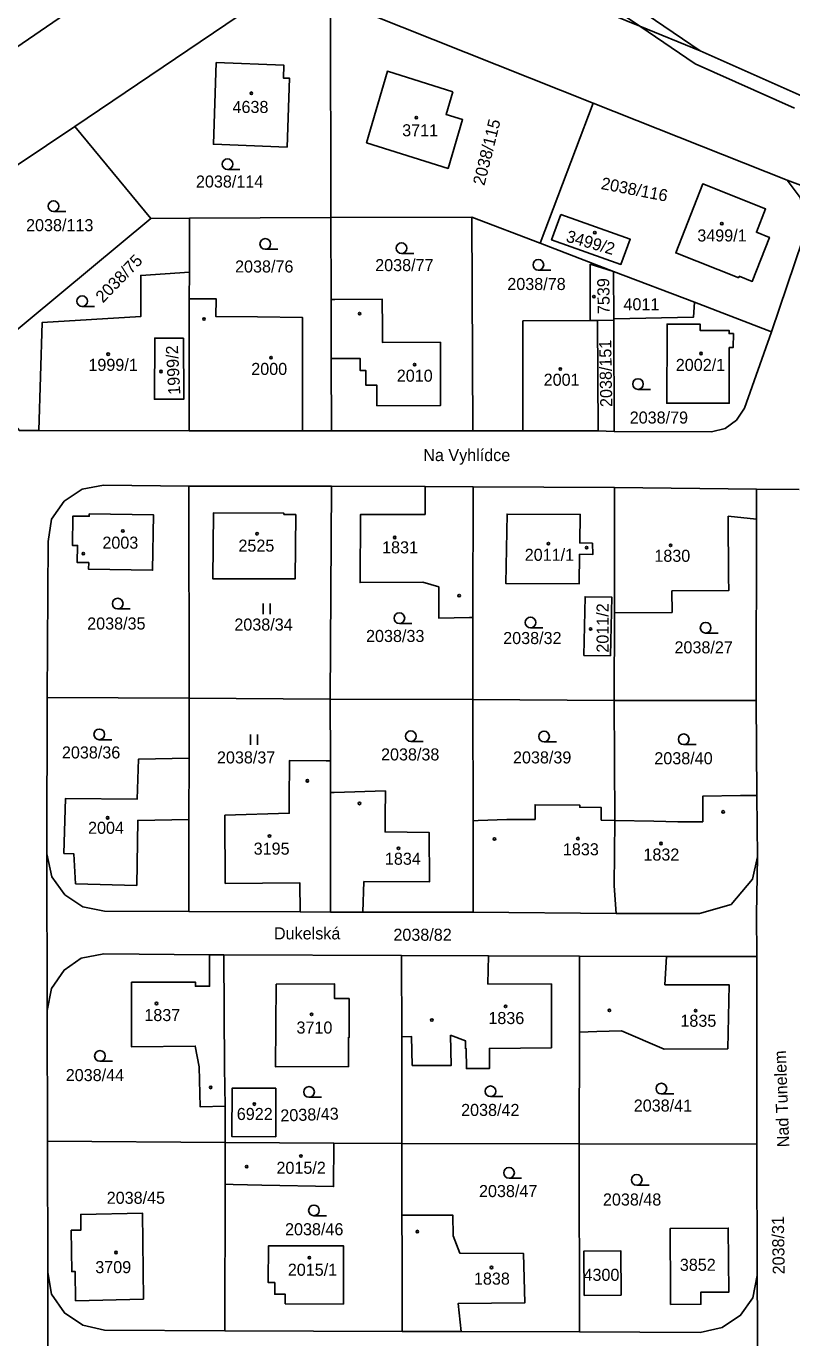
# Model space of a CAD drawing. Extents: x -667048 to -665920, y -1108425 to -1107247.
# Drawn here: x -666112.2 to -666004.4, y -1107911.7 to -1107726.9 of the extents above; entities that cross this region are included whole.
import ezdxf

# ---------------------------------------------------------------- set-up
doc = ezdxf.new("R2010")
doc.units = 0
for name, color, linetype in [('Default', 7, 'Continuous'), ('Hranice parcel', 7, 'Continuous'), ('Parcelní čísla', 7, 'Continuous'), ('Pop_ PČ_ popisy', 7, 'Continuous'), ('Značky budov', 7, 'Continuous'), ('Značky kultur', 7, 'Continuous')]:
    doc.layers.add(name, color=color, linetype=linetype)

# ---------------------------------------------------------------- blocks, each defined once
blk = doc.blocks.new('3.041')
at = {"layer": 'Default'}
blk.add_line((8, 0), (1758, 0), dxfattribs=at)
blk.add_circle((8, 750), 750, dxfattribs=at)
blk = doc.blocks.new('4.021')
at = {"layer": 'Default'}
blk.add_circle((-7, 1), 175, dxfattribs=at)
blk = doc.blocks.new('3.061')
at = {"layer": 'Default'}
for p, q in [((-511, -1), (-511, 1499)), ((489, -1), (489, 1499))]:
    blk.add_line(p, q, dxfattribs=at)

msp = doc.modelspace()

# ---------------------------------------------------------------- linework, layer by layer
at = {"layer": 'Hranice parcel'}
for points in [[(-666025.82, -1107726.88), (-666057.69, -1107713.89), (-666060.4, -1107712.81)], [(-666099.11, -1107719.88), (-666160.69, -1107762.11)], [(-666032.37, -1107737.69), (-666063.88, -1107725.17), (-666069.37, -1107723.76)], [(-666069.32, -1107753.84), (-666069.37, -1107723.76)], [(-666029.5, -1107724.39), (-666025.82, -1107726.88)], [(-666082.41, -1107725.44), (-666105.42, -1107741.01)], [(-666024.91, -1107725.17), (-666017.32, -1107730.34)], [(-666025.82, -1107726.88), (-666018.01, -1107732.17), (-666004.04, -1107738.39)], [(-666017.32, -1107730.34), (-666025.82, -1107726.88)], [(-665927.32, -1107807.05), (-665936.22, -1107797.25), (-665949.88, -1107782.67), (-665960.81, -1107771.82), (-665971.71, -1107761.69), (-665984.47, -1107750.77), (-665995.85, -1107741.81), (-666002.94, -1107736.71), (-666017.32, -1107730.34)], [(-666075.51, -1107743.9), (-666085.88, -1107743.49), (-666085.48, -1107731.98), (-666075.95, -1107732.36), (-666076.02, -1107734.17), (-666075.16, -1107734.2), (-666075.51, -1107743.9)], [(-666052.16, -1107736.1), (-666053.11, -1107739.29), (-666050.78, -1107740.02), (-666052.82, -1107746.9), (-666064.31, -1107743.29), (-666061.36, -1107733.22), (-666052.16, -1107736.1)], [(-666039.84, -1107757.44), (-666032.37, -1107737.69)], [(-666005.07, -1107748.54), (-666032.37, -1107737.69)], [(-666105.42, -1107741.01), (-666133.53, -1107759.84)], [(-666094.68, -1107753.95), (-666105.42, -1107741.01)], [(-666005.07, -1107748.54), (-666003.24, -1107750.99), (-666002.46, -1107753.88), (-666002.9, -1107757.03), (-666007.26, -1107769.91)], [(-665986.51, -1107755.5), (-666005.07, -1107748.54)], [(-666011.89, -1107762.34), (-666020.75, -1107758.81), (-666016.96, -1107749.08), (-666008.09, -1107752.62), (-666009.38, -1107755.91), (-666007.56, -1107756.63), (-666009.98, -1107762.83), (-666011.8, -1107762.11), (-666011.89, -1107762.34)], [(-666094.68, -1107753.95), (-666120.36, -1107775.31)], [(-666089.26, -1107753.93), (-666094.68, -1107753.95)], [(-666089.27, -1107761.53), (-666089.26, -1107753.93)], [(-666069.32, -1107753.84), (-666089.26, -1107753.93)], [(-666049.46, -1107753.75), (-666069.32, -1107753.84)], [(-666069.3, -1107765.39), (-666069.32, -1107753.84)], [(-666039.84, -1107757.44), (-666049.46, -1107753.75)], [(-666049.33, -1107783.86), (-666049.46, -1107753.75)], [(-666036.93, -1107753.42), (-666027.17, -1107756.88), (-666028.48, -1107760.44), (-666038.24, -1107756.99), (-666036.93, -1107753.42)], [(-666029.5, -1107761.42), (-666039.84, -1107757.44)], [(-666110.45, -1107783.85), (-666110.01, -1107768.63), (-666096.1, -1107767.77), (-666096.12, -1107761.98), (-666089.27, -1107761.53)], [(-666089.27, -1107761.53), (-666089.28, -1107765.28)], [(-666032.79, -1107768.34), (-666032.83, -1107760.38)], [(-666032.83, -1107760.38), (-666029.5, -1107761.42)], [(-666029.5, -1107761.42), (-666029.47, -1107768.11)], [(-666029.5, -1107761.42), (-666018.1, -1107765.77)], [(-666089.31, -1107783.86), (-666089.28, -1107765.28)], [(-666089.28, -1107765.28), (-666088.91, -1107765.28), (-666085.51, -1107765.28), (-666085.53, -1107767.78), (-666079.69, -1107767.84), (-666073.35, -1107767.9), (-666073.32, -1107780.3), (-666073.34, -1107783.86)], [(-666069.3, -1107765.39), (-666068.79, -1107765.39), (-666062.09, -1107765.35), (-666062.08, -1107769.4), (-666062.08, -1107771.43), (-666053.9, -1107771.4), (-666053.88, -1107780.3), (-666062.85, -1107780.34), (-666062.85, -1107777.46), (-666064.39, -1107777.47), (-666064.39, -1107775.4), (-666065.2, -1107775.4), (-666065.2, -1107773.69), (-666069.28, -1107773.71)], [(-666069.28, -1107773.71), (-666069.3, -1107765.39)], [(-666018.1, -1107765.77), (-666018.27, -1107767.88), (-666029.47, -1107768.11)], [(-666007.26, -1107769.91), (-666018.1, -1107765.77)], [(-666042.31, -1107783.86), (-666042.29, -1107779.88), (-666042.29, -1107772.16), (-666042.28, -1107768.4), (-666032.79, -1107768.34)], [(-666031.78, -1107768.33), (-666032.79, -1107768.34)], [(-666031.78, -1107768.33), (-666029.47, -1107768.3)], [(-666031.69, -1107783.87), (-666031.78, -1107768.33)], [(-666029.47, -1107768.11), (-666029.47, -1107768.3)], [(-666029.47, -1107768.3), (-666029.41, -1107783.96)], [(-666021.97, -1107769.76), (-666021.98, -1107768.84), (-666017.33, -1107768.83), (-666017.32, -1107769.73), (-666013.24, -1107769.73), (-666013.24, -1107770.19), (-666012.63, -1107770.19), (-666012.67, -1107772.14), (-666013.23, -1107772.14)], [(-666029.41, -1107783.96), (-666015.74, -1107784.01), (-666013.81, -1107783.55), (-666012.18, -1107782.36), (-666011.07, -1107780.67), (-666007.26, -1107769.91)], [(-666013.23, -1107772.14), (-666013.22, -1107779.99), (-666022.03, -1107780), (-666021.97, -1107769.76)], [(-666090.08, -1107770.82), (-666090.06, -1107779.43), (-666094.19, -1107779.43), (-666094.15, -1107770.82), (-666090.08, -1107770.82)], [(-666069.26, -1107783.86), (-666069.28, -1107773.71)], [(-666120.36, -1107775.31), (-666113.2, -1107783.85), (-666110.45, -1107783.85)], [(-666089.31, -1107783.86), (-666110.45, -1107783.85)], [(-666073.34, -1107783.86), (-666089.31, -1107783.86)], [(-666073.34, -1107783.86), (-666069.26, -1107783.86)], [(-666069.26, -1107783.86), (-666049.33, -1107783.86)], [(-666049.33, -1107783.86), (-666042.31, -1107783.86)], [(-666031.69, -1107783.87), (-666042.31, -1107783.86)], [(-666029.41, -1107783.96), (-666031.69, -1107783.87)], [(-666109.3, -1107821.45), (-666109.14, -1107799.46), (-666108.69, -1107796.33), (-666106.92, -1107793.8), (-666104.38, -1107792.08), (-666101.34, -1107791.52), (-666089.33, -1107791.67)], [(-666089.33, -1107791.67), (-666089.29, -1107821.55)], [(-666089.33, -1107791.67), (-666069.25, -1107791.68)], [(-666069.25, -1107791.68), (-666069.42, -1107821.7)], [(-666056.06, -1107791.73), (-666069.25, -1107791.68)], [(-666056.07, -1107795.67), (-666056.06, -1107791.73)], [(-666056.06, -1107791.73), (-666049.3, -1107791.76)], [(-666049.3, -1107791.76), (-666049.34, -1107810.21)], [(-666049.3, -1107791.76), (-666029.36, -1107791.89)], [(-666029.4, -1107809.53), (-666029.36, -1107791.89)], [(-666029.36, -1107791.89), (-666009.37, -1107792.09)], [(-666009.37, -1107792.09), (-666009.38, -1107796.32)], [(-666003.37, -1107792.16), (-666009.37, -1107792.09)], [(-666103.38, -1107795.58), (-666103.38, -1107795.93), (-666105.69, -1107795.92), (-666105.71, -1107800.05), (-666105.02, -1107800.03), (-666105.06, -1107802.44), (-666103.45, -1107802.46), (-666103.46, -1107803.38), (-666094.46, -1107803.52), (-666094.34, -1107795.71), (-666103.38, -1107795.58)], [(-666075.97, -1107795.67), (-666075.97, -1107795.47), (-666085.88, -1107795.45), (-666085.96, -1107804.74), (-666076.08, -1107804.75), (-666074.38, -1107804.75), (-666074.28, -1107795.69), (-666075.97, -1107795.67)], [(-666056.37, -1107805.23), (-666065.21, -1107805.27), (-666065.15, -1107795.65), (-666056.07, -1107795.67)], [(-666032.47, -1107799.7), (-666034.27, -1107799.68), (-666034.21, -1107795.67), (-666044.52, -1107795.62), (-666044.7, -1107805.38), (-666034.35, -1107805.44), (-666034.3, -1107801.28), (-666032.44, -1107801.31), (-666032.47, -1107799.7)], [(-666013.38, -1107795.91), (-666013.32, -1107804.49), (-666013.26, -1107806.38), (-666021.32, -1107806.44)], [(-666009.38, -1107796.32), (-666013.38, -1107795.91)], [(-666009.41, -1107821.89), (-666009.38, -1107796.32)], [(-666049.34, -1107810.21), (-666049.8, -1107810.21), (-666054.14, -1107810.26), (-666054.15, -1107805.87), (-666056.37, -1107805.23)], [(-666033.72, -1107815.53), (-666029.96, -1107815.58), (-666029.77, -1107807.31), (-666033.53, -1107807.26), (-666033.72, -1107815.53)], [(-666021.32, -1107806.44), (-666021.26, -1107809.47), (-666029.4, -1107809.53)], [(-666029.4, -1107809.53), (-666029.43, -1107821.86)], [(-666049.36, -1107821.75), (-666049.34, -1107810.21)], [(-666109.3, -1107821.45), (-666109.35, -1107843.47)], [(-666089.29, -1107821.55), (-666109.3, -1107821.45)], [(-666089.31, -1107830.03), (-666089.29, -1107821.55)], [(-666089.29, -1107821.55), (-666069.42, -1107821.7)], [(-666069.42, -1107821.7), (-666049.36, -1107821.75)], [(-666069.41, -1107830.38), (-666069.42, -1107821.7)], [(-666049.31, -1107838.83), (-666049.36, -1107821.75)], [(-666049.36, -1107821.75), (-666029.43, -1107821.86)], [(-666029.43, -1107821.86), (-666029.33, -1107838.78)], [(-666029.43, -1107821.86), (-666009.41, -1107821.89)], [(-666009.41, -1107821.89), (-666009.31, -1107835.27)], [(-666089.33, -1107838.64), (-666096.53, -1107838.77), (-666096.69, -1107847.94), (-666105.29, -1107847.7), (-666105.53, -1107843.51), (-666106.95, -1107843.43), (-666106.71, -1107835.69), (-666096.61, -1107835.77), (-666096.45, -1107830.17), (-666089.31, -1107830.03)], [(-666089.31, -1107830.03), (-666089.33, -1107838.64)], [(-666069.41, -1107830.38), (-666070.02, -1107830.37), (-666075.15, -1107830.32), (-666075.19, -1107836.06), (-666075.2, -1107837.78), (-666084.27, -1107838.06), (-666084.22, -1107847.66), (-666073.69, -1107847.6), (-666073.67, -1107851.68)], [(-666069.4, -1107834.85), (-666069.41, -1107830.38)], [(-666064.81, -1107851.7), (-666064.69, -1107847.41), (-666055.42, -1107847.42), (-666055.5, -1107840.48), (-666061.71, -1107840.41), (-666061.69, -1107838.23), (-666061.65, -1107834.63), (-666068.86, -1107834.83), (-666069.4, -1107834.85)], [(-666069.4, -1107834.85), (-666069.38, -1107851.69)], [(-666020.44, -1107838.97), (-666017.78, -1107838.98), (-666016.94, -1107838.98), (-666016.93, -1107835.35), (-666011.63, -1107835.29), (-666009.31, -1107835.27)], [(-666009.31, -1107835.27), (-666009.24, -1107843.93)], [(-666029.33, -1107838.78), (-666031.24, -1107838.74), (-666031.26, -1107836.98), (-666034.27, -1107836.93), (-666034.26, -1107836.64), (-666040.57, -1107836.57), (-666040.58, -1107838.63), (-666044.54, -1107838.66), (-666048.59, -1107838.8), (-666049.31, -1107838.83)], [(-666089.35, -1107851.64), (-666089.33, -1107838.64)], [(-666049.31, -1107838.83), (-666049.28, -1107851.73)], [(-666029.13, -1107851.88), (-666029.45, -1107848.01), (-666029.33, -1107838.78)], [(-666029.33, -1107838.78), (-666023.86, -1107838.9), (-666020.44, -1107838.97)], [(-666109.35, -1107843.47), (-666108.62, -1107846.72), (-666106.81, -1107849.25), (-666104.26, -1107850.95), (-666101.2, -1107851.55), (-666089.35, -1107851.64)], [(-666109.32, -1107865.58), (-666109.35, -1107843.47)], [(-666009.24, -1107843.93), (-666009.94, -1107847.04), (-666012.95, -1107850.61), (-666017.43, -1107851.9), (-666029.13, -1107851.88)], [(-666009.24, -1107843.93), (-666009.39, -1107852.06), (-666009.31, -1107857.96)], [(-666089.35, -1107851.64), (-666073.67, -1107851.68)], [(-666073.67, -1107851.68), (-666069.38, -1107851.69)], [(-666069.38, -1107851.69), (-666064.81, -1107851.7)], [(-666064.81, -1107851.7), (-666049.28, -1107851.73)], [(-666049.28, -1107851.73), (-666029.13, -1107851.88)], [(-666086.41, -1107857.7), (-666101.32, -1107857.59), (-666104.49, -1107858.21), (-666106.92, -1107859.87), (-666108.71, -1107862.47), (-666109.32, -1107865.58)], [(-666086.41, -1107857.7), (-666086.42, -1107862.14), (-666088.42, -1107862.14), (-666088.42, -1107861.57), (-666097.4, -1107861.58), (-666097.43, -1107870.67), (-666088.43, -1107870.57), (-666087.88, -1107873.5), (-666087.75, -1107879.14), (-666084.23, -1107879.07)], [(-666084.4, -1107857.71), (-666086.41, -1107857.7)], [(-666084.23, -1107879.07), (-666084.34, -1107873.6), (-666084.4, -1107857.71)], [(-666059.37, -1107857.83), (-666084.4, -1107857.71)], [(-666059.35, -1107869.26), (-666059.37, -1107857.83)], [(-666059.37, -1107857.83), (-666047.14, -1107857.87)], [(-666047.14, -1107857.87), (-666047.23, -1107861.81), (-666038.24, -1107861.84), (-666038.27, -1107870.82), (-666047, -1107870.92), (-666046.97, -1107873.72), (-666050.23, -1107873.76), (-666050.26, -1107870.96), (-666050.38, -1107870.97)], [(-666034.29, -1107857.92), (-666047.14, -1107857.87)], [(-666034.32, -1107868.6), (-666034.29, -1107857.92)], [(-666034.32, -1107868.6), (-666031.85, -1107868.52), (-666028.38, -1107868.41), (-666022.4, -1107871), (-666013.44, -1107870.96), (-666013.23, -1107861.96), (-666022.29, -1107861.93), (-666022.08, -1107857.94)], [(-666022.08, -1107857.94), (-666034.29, -1107857.92)], [(-666009.31, -1107857.96), (-666022.08, -1107857.94)], [(-666009.31, -1107857.96), (-666009.31, -1107884.42)], [(-666077.06, -1107861.85), (-666077.14, -1107873.5), (-666066.84, -1107873.48), (-666066.85, -1107869.33), (-666066.75, -1107869.33), (-666066.76, -1107863.88), (-666068.81, -1107863.88), (-666068.81, -1107861.83), (-666077.06, -1107861.85)], [(-666109.27, -1107883.99), (-666109.32, -1107865.58)], [(-666034.36, -1107884.35), (-666034.32, -1107868.6)], [(-666052.5, -1107869.04), (-666052.39, -1107873.34), (-666057.87, -1107873.3), (-666058, -1107869.22), (-666059.35, -1107869.26)], [(-666059.35, -1107869.26), (-666059.32, -1107884.33)], [(-666050.38, -1107870.97), (-666050.38, -1107869.83), (-666052.5, -1107869.04)], [(-666077.11, -1107883.37), (-666083.29, -1107883.31), (-666083.25, -1107876.53), (-666077.09, -1107876.52), (-666077.11, -1107883.37)], [(-666084.23, -1107879.07), (-666084.22, -1107884.18)], [(-666084.22, -1107884.18), (-666109.27, -1107883.99)], [(-666109.27, -1107883.99), (-666109.22, -1107902.47)], [(-666084.23, -1107890.05), (-666084.22, -1107884.18)], [(-666084.23, -1107890.05), (-666083.1, -1107890.07), (-666079.05, -1107890.16), (-666068.96, -1107890.37), (-666068.92, -1107884.27)], [(-666068.92, -1107884.27), (-666084.22, -1107884.18)], [(-666068.92, -1107884.27), (-666059.32, -1107884.33)], [(-666059.32, -1107894.39), (-666059.32, -1107884.33)], [(-666059.32, -1107884.33), (-666034.36, -1107884.35)], [(-666034.31, -1107910.87), (-666034.36, -1107884.35)], [(-666034.36, -1107884.35), (-666009.31, -1107884.42)], [(-666009.31, -1107884.42), (-666009.29, -1107902.93)], [(-666084.26, -1107910.72), (-666084.23, -1107890.05)], [(-666105.91, -1107896.53), (-666104.54, -1107896.5), (-666104.57, -1107894.31), (-666095.86, -1107894.13), (-666095.73, -1107906.24), (-666105.29, -1107906.46), (-666105.34, -1107902.36), (-666105.83, -1107902.37), (-666105.91, -1107896.53)], [(-666050.98, -1107910.82), (-666051.4, -1107906.84), (-666042.02, -1107906.77), (-666042.22, -1107899.79), (-666051.19, -1107899.76), (-666052.11, -1107897.31), (-666052.16, -1107894.39), (-666059.32, -1107894.39)], [(-666059.32, -1107894.39), (-666059.31, -1107900.09), (-666059.31, -1107910.79)], [(-666021.5, -1107907), (-666021.51, -1107905.32), (-666021.53, -1107896.28), (-666013.35, -1107896.23), (-666013.27, -1107905.24), (-666017.23, -1107905.28), (-666017.22, -1107906.96), (-666021.5, -1107907)], [(-666067.57, -1107906.94), (-666067.54, -1107898.74), (-666078.13, -1107898.75), (-666078.15, -1107903.9), (-666077.24, -1107903.9), (-666077.24, -1107905.55), (-666075.77, -1107905.56), (-666075.77, -1107906.91)], [(-666033.64, -1107905.71), (-666033.68, -1107899.47), (-666028.48, -1107899.44), (-666028.44, -1107905.68)], [(-666109.14, -1107924.68), (-666109.22, -1107902.47)], [(-666109.22, -1107902.47), (-666108.7, -1107905.56), (-666106.87, -1107908.19), (-666104.29, -1107909.89), (-666101.21, -1107910.63), (-666084.26, -1107910.72)], [(-666034.31, -1107910.87), (-666017.31, -1107910.92), (-666014.2, -1107910.23), (-666011.62, -1107908.51), (-666009.9, -1107906.04), (-666009.29, -1107902.93)], [(-666009.29, -1107902.93), (-666009.17, -1107916.92)], [(-666028.44, -1107905.68), (-666033.64, -1107905.71)], [(-666075.77, -1107906.91), (-666067.57, -1107906.94)], [(-666084.26, -1107910.72), (-666059.31, -1107910.79)], [(-666059.31, -1107910.79), (-666050.98, -1107910.82)], [(-666050.98, -1107910.82), (-666034.31, -1107910.87)]]:
    msp.add_lwpolyline(points, dxfattribs=at)

# ---------------------------------------------------------------- block references
at = {"layer": 'Značky budov', "xscale": 0.0010000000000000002, "yscale": 0.0010000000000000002}
for p in [(-666080.53, -1107736.31), (-666057.29, -1107739.75), (-666032.15, -1107755.96), (-666014.25, -1107754.69), (-666032.28, -1107764.98), (-666087.19, -1107768.13), (-666065.28, -1107767.36), (-666100.7, -1107773.08), (-666077.75, -1107773.58), (-666057.53, -1107774.55), (-666017.18, -1107772.99), (-666093.26, -1107775.52), (-666037.01, -1107775.18), (-666098.63, -1107797.99), (-666079.72, -1107798.39), (-666060.33, -1107798.92), (-666038.68, -1107799.79), (-666033.3, -1107800.35), (-666021.47, -1107800.03), (-666104.2, -1107801.18), (-666051.26, -1107807.12), (-666032.74, -1107811.8), (-666072.64, -1107833.21), (-666065.3, -1107836.39), (-666100.77, -1107838.42), (-666014.07, -1107837.58), (-666077.97, -1107840.99), (-666059.8, -1107842.71), (-666046.28, -1107841.4), (-666034.53, -1107841.34), (-666022.83, -1107842.03), (-666093.89, -1107864.58), (-666044.72, -1107864.98), (-666072.05, -1107866.12), (-666055.11, -1107866.92), (-666030.09, -1107865.54), (-666017.95, -1107865.6), (-666086.25, -1107876.41), (-666080.11, -1107878.76), (-666073.55, -1107886.08), (-666081.18, -1107887.58), (-666057.15, -1107896.72), (-666099.6, -1107899.67), (-666072.36, -1107900.41), (-666046.7, -1107901.79)]:
    msp.add_blockref('4.021', p, dxfattribs=at)
at = {"layer": 'Značky kultur', "xscale": 0.0010000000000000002, "yscale": 0.0010000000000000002}
for name, p in [('3.041', (-666083.9, -1107747.06)), ('3.041', (-666108.41, -1107752.97)), ('3.041', (-666078.58, -1107758.3)), ('3.041', (-666059.4, -1107758.89)), ('3.041', (-666040.11, -1107761.25)), ('3.041', (-666104.38, -1107766.37)), ('3.041', (-666026.08, -1107778.04)), ('3.041', (-666099.37, -1107808.98)), ('3.061', (-666078.36, -1107809.73)), ('3.041', (-666059.69, -1107811.03)), ('3.041', (-666041.23, -1107811.64)), ('3.041', (-666016.55, -1107812.38)), ('3.041', (-666101.97, -1107827.41)), ('3.041', (-666058.08, -1107827.66)), ('3.041', (-666039.31, -1107827.7)), ('3.061', (-666080.16, -1107828.15)), ('3.041', (-666019.64, -1107828.1)), ('3.041', (-666101.87, -1107872.72)), ('3.041', (-666022.79, -1107877.32)), ('3.041', (-666072.42, -1107877.8)), ('3.041', (-666046.85, -1107877.7)), ('3.041', (-666044.25, -1107889.19)), ('3.041', (-666026.26, -1107890.18)), ('3.041', (-666071.73, -1107894.49))]:
    msp.add_blockref(name, p, dxfattribs=at)

# ---------------------------------------------------------------- texts
at = {"layer": 'Parcelní čísla'}
for s, p in [('4638', (-666083.19, -1107739.09)), ('3711', (-666059.29, -1107742.38)), ('2038/114', (-666088.34, -1107749.6)), ('2038/113', (-666112.27, -1107755.75)), ('3499/1', (-666017.72, -1107757.2)), ('2038/77', (-666063.09, -1107761.38)), ('2038/76', (-666082.83, -1107761.57)), ('2038/78', (-666044.48, -1107764.04)), ('4011', (-666028.12, -1107766.9)), ('1999/1', (-666103.49, -1107775.43)), ('2000', (-666080.55, -1107776.01)), ('2002/1', (-666020.75, -1107775.44)), ('2010', (-666060.05, -1107776.96)), ('2001', (-666039.36, -1107777.53)), ('2038/79', (-666027.24, -1107782.86)), ('2003', (-666101.52, -1107800.49)), ('2525', (-666082.36, -1107800.91)), ('1831', (-666062.12, -1107801.15)), ('2011/1', (-666042.03, -1107802.2)), ('1830', (-666023.77, -1107802.34)), ('2038/35', (-666103.66, -1107811.88)), ('2038/34', (-666082.93, -1107812.03)), ('2038/33', (-666064.38, -1107813.64)), ('2038/32', (-666045.06, -1107813.93)), ('2038/27', (-666020.93, -1107815.24)), ('2038/36', (-666107.22, -1107830.05)), ('2038/37', (-666085.38, -1107830.75)), ('2038/38', (-666062.27, -1107830.33)), ('2038/39', (-666043.68, -1107830.75)), ('2038/40', (-666023.77, -1107830.87)), ('2004', (-666103.54, -1107840.67)), ('3195', (-666080.21, -1107843.61)), ('1833', (-666036.65, -1107843.7)), ('1832', (-666025.31, -1107844.44)), ('1834', (-666061.72, -1107845.03)), ('2038/82', (-666060.53, -1107855.74)), ('1837', (-666095.61, -1107867.06)), ('1836', (-666047.15, -1107867.48)), ('1835', (-666020.1, -1107867.86)), ('3710', (-666074.18, -1107868.82)), ('2038/44', (-666106.68, -1107875.52)), ('6922', (-666082.59, -1107881)), ('2038/42', (-666050.99, -1107880.43)), ('2038/41', (-666026.67, -1107879.81)), ('2015/2', (-666077, -1107888.58)), ('2038/47', (-666048.47, -1107891.86)), ('2038/45', (-666100.91, -1107892.81)), ('2038/48', (-666031.01, -1107893.05)), ('2038/46', (-666075.79, -1107897.24)), ('3709', (-666102.52, -1107902.58)), ('2015/1', (-666075.4, -1107902.95)), ('4300', (-666033.75, -1107903.66)), ('3852', (-666020.18, -1107902.25)), ('1838', (-666049.18, -1107904.2))]:
    msp.add_text(s, height=1.7, dxfattribs=at).set_placement(p)
for s, rotation, p in [('2038/115', 76, (-666047.71, -1107749.41)), ('2038/116', 349, (-666031.38, -1107749.79)), ('3499/2', 344, (-666036.32, -1107757.2)), ('2038/75', 46, (-666101.44, -1107765.94)), ('7539', 91, (-666030.04, -1107767.41)), ('1999/2', 93, (-666090.53, -1107778.75)), ('2038/151', 91, (-666029.69, -1107780.51)), ('2011/2', 90, (-666030.21, -1107815.14)), ('2038/43', 2, (-666076.42, -1107881.22)), ('2038/31', 91, (-666005.39, -1107902.74))]:
    msp.add_text(s, height=1.7, rotation=rotation, dxfattribs=at).set_placement(p)
at = {"layer": 'Pop_ PČ_ popisy'}
for s, p in [('Na Vyhlídce', (-666056.32, -1107788.15)), ('Dukelská', (-666077.35, -1107855.55))]:
    msp.add_text(s, height=1.7, dxfattribs=at).set_placement(p)
msp.add_text('Nad Tunelem', height=1.7, rotation=92, dxfattribs=at).set_placement((-666004.76, -1107884.81))

doc.saveas('drawing.dxf')
